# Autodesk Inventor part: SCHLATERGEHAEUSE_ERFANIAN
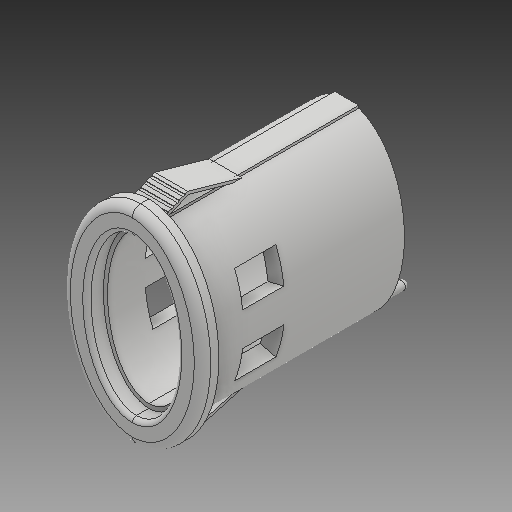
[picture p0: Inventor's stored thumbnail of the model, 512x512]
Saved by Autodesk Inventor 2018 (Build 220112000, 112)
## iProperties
Created: 2019-01
Part Number: SCHLATERGEHAEUSE_ERFANIAN
Material: Polypropylene (PP)
Document SubType Name: Modeling
Designer: zand
Density: 0.902188 g/cm^3
Appearance: Vorgabe
Mass: 2.13443 g
Surface Area: 33.7927 cm^2
Volume: 2.36584 cm^3
Author: zand
Revision Number: 9LAST_VERSION
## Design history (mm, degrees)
feature "Basis1"
node "Volumenkörper1"
